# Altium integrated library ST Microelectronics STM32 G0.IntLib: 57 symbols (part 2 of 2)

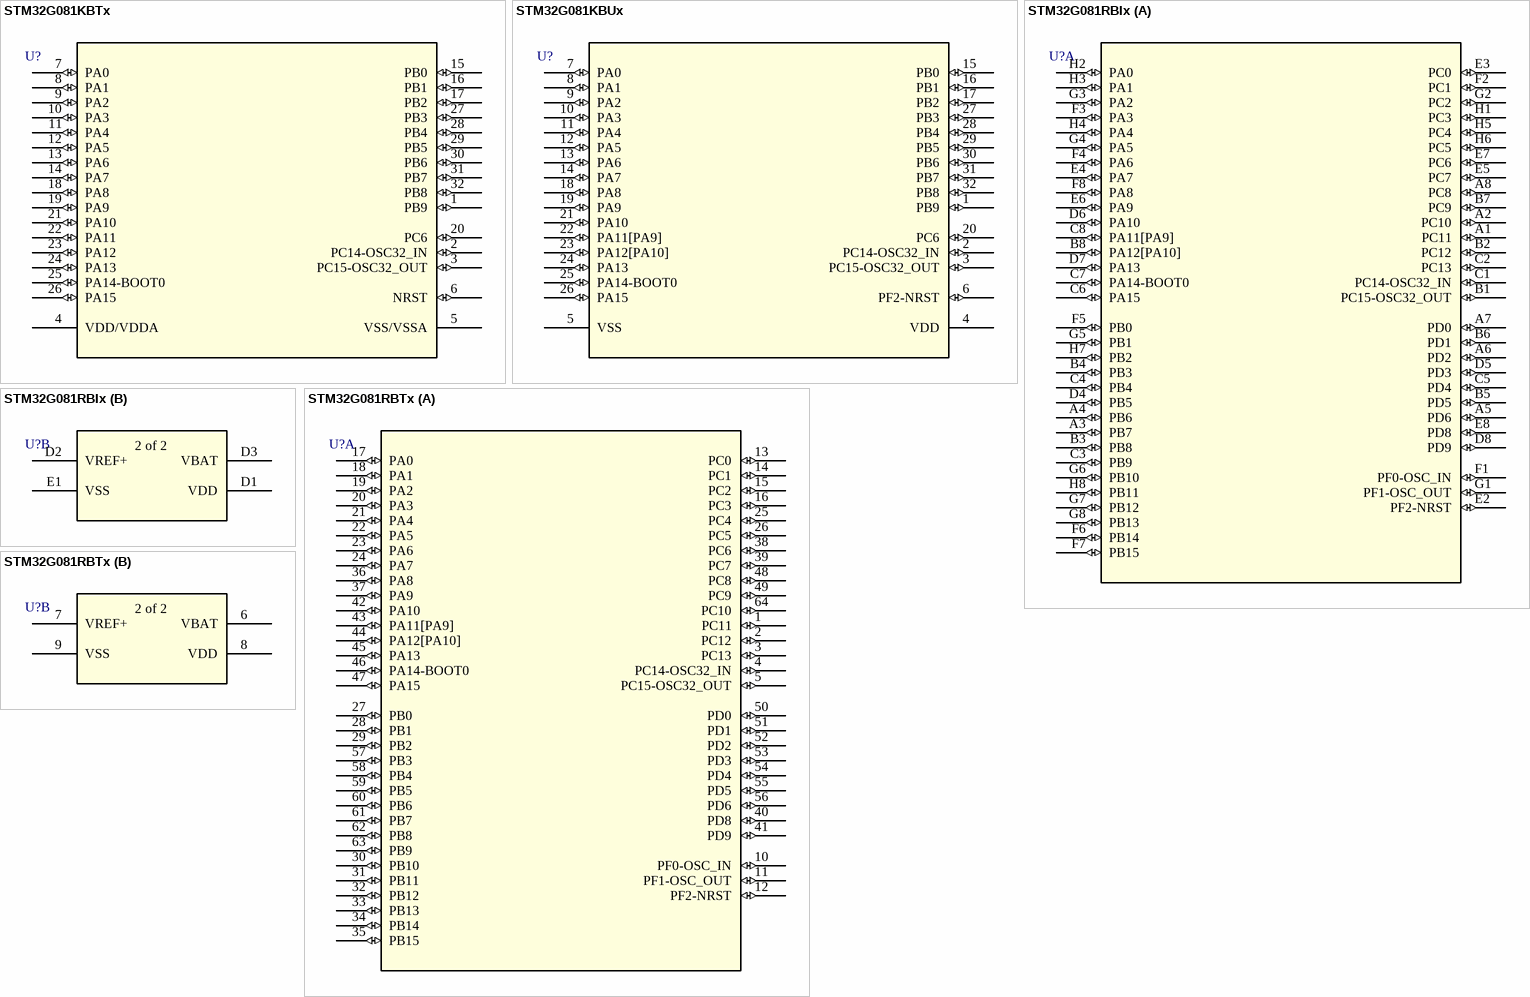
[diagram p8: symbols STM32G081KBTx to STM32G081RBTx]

## STM32G081KBTx
designator U?
The STM32G081xB mainstream microcontrollers are based on high-performance Arm® Cortex®-M0+ 32-bit RISC core operating at up to 64 MHz frequency. / 128 Kbytes of Flash program memory and 36 Kbytes of SRAM. With 32pin LQFP 7x7x1.4 package; Manufacturer_Part_Number: STM32G0_LQFP32_T2; Vendor: STMicroelectronics
footprint LQFP-32
pins: 1 PB9 (io), 2 PC14-OSC32_IN (io), 3 PC15-OSC32_OUT (io), 4 VDD/VDDA (power), 5 VSS/VSSA (power), 6 NRST (io), 7 PA0 (io), 8 PA1 (io), 9 PA2 (io), 10 PA3 (io), 11 PA4 (io), 12 PA5 (io), 13 PA6 (io), 14 PA7 (io), 15 PB0 (io), 16 PB1 (io), 17 PB2 (io), 18 PA8 (io), 19 PA9 (io), 20 PC6 (io), 21 PA10 (io), 22 PA11 (io), 23 PA12 (io), 24 PA13 (io), 25 PA14-BOOT0 (io), 26 PA15 (io), 27 PB3 (io), 28 PB4 (io), 29 PB5 (io), 30 PB6 (io), 31 PB7 (io), 32 PB8 (io)

## STM32G081KBUx
designator U?
The STM32G081xB mainstream microcontrollers are based on high-performance Arm® Cortex®-M0+ 32-bit RISC core operating at up to 64 MHz frequency. / 128 Kbytes of Flash program memory and 36 Kbytes of SRAM. With 32pin UFQFPN  5x5x0.55  package; Manufacturer_Part_Number: stm32g0_ufqfpn32_t1; Built_By: EMA_Jessica; Vendor: STMicroelectronics
footprint UFQFPN-32
pins: 1 PB9 (io), 2 PC14-OSC32_IN (io), 3 PC15-OSC32_OUT (io), 4 VDD (power), 5 VSS (power), 6 PF2-NRST (io), 7 PA0 (io), 8 PA1 (io), 9 PA2 (io), 10 PA3 (io), 11 PA4 (io), 12 PA5 (io), 13 PA6 (io), 14 PA7 (io), 15 PB0 (io), 16 PB1 (io), 17 PB2 (io), 18 PA8 (io), 19 PA9 (io), 20 PC6 (io), 21 PA10 (io), 22 PA11[PA9] (io), 23 PA12[PA10] (io), 24 PA13 (io), 25 PA14-BOOT0 (io), 26 PA15 (io), 27 PB3 (io), 28 PB4 (io), 29 PB5 (io), 30 PB6 (io), 31 PB7 (io), 32 PB8 (io)

## STM32G081RBIx
designator U?
The STM32G081xB mainstream microcontrollers are based on high-performance Arm® Cortex®-M0+ 32-bit RISC core operating at up to 64 MHz frequency. / 128 Kbytes of Flash program memory and 36 Kbytes of SRAM. With 64pin UFBGA 5x5x0.5 package; Manufacturer_Part_Number: stm32g0_ufbga64_t1; Built_By: EMA_Jessica; Vendor: STMicroelectronics
footprint UFBGA64-5x5mm
part A pins: A1 PC11 (io), A2 PC10 (io), A3 PB7 (io), A4 PB6 (io), A5 PD6 (io), A6 PD2 (io), A7 PD0 (io), A8 PC8 (io), B1 PC15-OSC32_OUT (io), B2 PC12 (io), B3 PB8 (io), B4 PB3 (io), B5 PD5 (io), B6 PD1 (io), B7 PC9 (io), B8 PA12[PA10] (io), C1 PC14-OSC32_IN (io), C2 PC13 (io), C3 PB9 (io), C4 PB4 (io), C5 PD4 (io), C6 PA15 (io), C7 PA14-BOOT0 (io), C8 PA11[PA9] (io), D4 PB5 (io), D5 PD3 (io), D6 PA10 (io), D7 PA13 (io), D8 PD9 (io), E2 PF2-NRST (io), E3 PC0 (io), E4 PA7 (io), E5 PC7 (io), E6 PA9 (io), E7 PC6 (io), E8 PD8 (io), F1 PF0-OSC_IN (io), F2 PC1 (io), F3 PA3 (io), F4 PA6 (io), F5 PB0 (io), F6 PB14 (io), F7 PB15 (io), F8 PA8 (io), G1 PF1-OSC_OUT (io), G2 PC2 (io), G3 PA2 (io), G4 PA5 (io), G5 PB1 (io), G6 PB10 (io), G7 PB12 (io), G8 PB13 (io), H1 PC3 (io), H2 PA0 (io), H3 PA1 (io), H4 PA4 (io), H5 PC4 (io), H6 PC5 (io), H7 PB2 (io), H8 PB11 (io)
part B pins: D1 VDD (power), D2 VREF+ (power), D3 VBAT (power), E1 VSS (power)

## STM32G081RBTx
designator U?
The STM32G081xB mainstream microcontrollers are based on high-performance Arm® Cortex®-M0+ 32-bit RISC core operating at up to 64 MHz frequency. / 128 Kbytes of Flash program memory and 36 Kbytes of SRAM. With 64pin LQFP 10x10x1.4 package; Manufacturer_Part_Number: stm32g0_lqfp64_t1; Built_By: EMA_Jessica; Vendor: STMicroelectronics
footprint LQFP-64
part A pins: 1 PC11 (io), 2 PC12 (io), 3 PC13 (io), 4 PC14-OSC32_IN (io), 5 PC15-OSC32_OUT (io), 10 PF0-OSC_IN (io), 11 PF1-OSC_OUT (io), 12 PF2-NRST (io), 13 PC0 (io), 14 PC1 (io), 15 PC2 (io), 16 PC3 (io), 17 PA0 (io), 18 PA1 (io), 19 PA2 (io), 20 PA3 (io), 21 PA4 (io), 22 PA5 (io), 23 PA6 (io), 24 PA7 (io), 25 PC4 (io), 26 PC5 (io), 27 PB0 (io), 28 PB1 (io), 29 PB2 (io), 30 PB10 (io), 31 PB11 (io), 32 PB12 (io), 33 PB13 (io), 34 PB14 (io), 35 PB15 (io), 36 PA8 (io), 37 PA9 (io), 38 PC6 (io), 39 PC7 (io), 40 PD8 (io), 41 PD9 (io), 42 PA10 (io), 43 PA11[PA9] (io), 44 PA12[PA10] (io), 45 PA13 (io), 46 PA14-BOOT0 (io), 47 PA15 (io), 48 PC8 (io), 49 PC9 (io), 50 PD0 (io), 51 PD1 (io), 52 PD2 (io), 53 PD3 (io), 54 PD4 (io), 55 PD5 (io), 56 PD6 (io), 57 PB3 (io), 58 PB4 (io), 59 PB5 (io), 60 PB6 (io), 61 PB7 (io), 62 PB8 (io), 63 PB9 (io), 64 PC10 (io)
part B pins: 6 VBAT (power), 7 VREF+ (power), 8 VDD (power), 9 VSS (power)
